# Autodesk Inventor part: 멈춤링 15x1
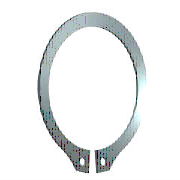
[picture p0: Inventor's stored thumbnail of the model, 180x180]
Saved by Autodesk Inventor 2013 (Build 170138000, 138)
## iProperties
Created: 2015-09
Part Number: 멈춤링 15x1
Material: 강철, 연강
Description: 리테이닝 링(C형)
Document SubType Name: Modeling
Standard: KS B 1336
Designer: mm
Standards Organization: KS
Language: ko-KR
Size Designation: 15 x 1
Categories: <MemberInstance><Categories><Category DisplayName="샤프트 부품" InternalName="7f7aeb1f-a693-4053-b835-cee3144e0d98" Mnemonic="SHFT"><Category DisplayName="써클립" Inter
Density: 1 g/cm^3
IsCustomPart: 1
Author: mduedu
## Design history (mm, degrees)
sketch "스케치1"
  geometry: L1 (-6, 0)-(6, 0) reference; L2 (0, 20.189)-(0, -80.536) reference; L3 (-48.09, 0)-(48.09, 0) reference; L4 (-0.425, -14.637)-(-0.425, -18.137); L5 (-0.425, -6.54)-(-0.425, -13.29); L6 (-2.795, 2.1)-(3.672, 2.1); L7 (0.425, -6.54)-(0.425, -13.29); L8 (0.425, -14.637)-(0.425, -18.137); C1 r 0.85 at (-1.7, -16.283); C2 r 0.85 at (1.7, -16.283); A1 r 7.15 centre (0, -7.5) between (0.425, -14.637) and (-0.425, -14.637); A2 r 9.075 centre (0, -6.975) between (4.291, -14.971) and (-4.291, -14.971); A3 r 10.646 centre (0, -7.5) between (-2.023, -17.952) and (-0.425, -18.137); A4 r 1.7 centre (-1.7, -16.283) between (-3.397, -16.376) and (-2.023, -17.952); A5 r 1.7 centre (-5.095, -16.469) between (-3.397, -16.376) and (-4.291, -14.971); A6 r 1.7 centre (5.095, -16.469) between (4.291, -14.971) and (3.397, -16.376); A7 r 1.7 centre (1.7, -16.283) between (2.023, -17.952) and (3.397, -16.376); A8 r 10.646 centre (0, -7.5) between (0.425, -18.137) and (2.023, -17.952)
  constraints: 16 point on circle, 12 end point, 10 centre point, 9 symmetric about line, 5 point on line, 4 tangent, 3 coincident, 2 horizontal, 1 perpendicular, 1 vertical, 5 other
  dimensions: "d0" = 14.3 diameter of A1 (= ND); "d1" = 3.5 distance of L4.end L4.start (= SRB2); "d6" = 0.425 distance between parallel lines of L2 L5 (= 0.25 x SD5); "d7" = 2.1 distance between parallel lines of L6 L3 (= SRB1); "d8" = 0.525 distance of A1.centre A2.centre (= 0.25 x SRB1); "d9" = 1.7 radius of A4 (= SD5); "d10" = 1.7 radius of A5 (= SD5); "d11" = 1.275 distance from line of L4 A4.centre (= 0.75 x SD5); "d12" = 1.7 diameter of C1 (= SD5); "d13" = 1.7 diameter of C2 (= SD5); "d14" = 7.5 distance from line of A1.centre L1 (= 0.5 x WD)
extrude "본체" new body sketch "스케치1" distance "d2" = 1 (= SD); taper "d3" = 0 deg
workaxis "Work Axis1"
workplane "Work Plane1"
body "Solid1"
other parameters: "WD" = 15 (= WDMIN) [user parameter; used in 1 equation term], "SD" = 1 [user parameter; used in 1 equation term], "SRB1" = 2.1 [user parameter; used in 2 equation terms], "ND" = 14.3 [user parameter; used in 1 equation term], "SRB2" = 3.5 [user parameter; used in 1 equation term], "SD5" = 1.7 [user parameter; used in 6 equation terms], "d15" = 0, "d16" = 0, "d17" = 0, "d41" = 0, "d42" = 0, "WDMIN" = 15 [user parameter; used in 1 equation term], "SD3" = 13.8 [user parameter], "WDMAX" = 16 [user parameter]
